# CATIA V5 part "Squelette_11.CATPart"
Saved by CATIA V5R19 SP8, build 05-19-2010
Part number: Squelette_11
Publications: "Diamètre 9-10", "Diamètre 9-11", "Plan dessous", "Plan 9-11", "Plan 9-10 gauche", "Plan 9-10 droite", "Plan profondeur 9-10", "Plan face 11", "ab", "ar"
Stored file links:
  J:\CFAO_IFMA\Squelette_11.CATPart
  J:\CFAO_IFMA\Squelette.CATProduct
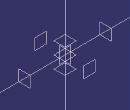
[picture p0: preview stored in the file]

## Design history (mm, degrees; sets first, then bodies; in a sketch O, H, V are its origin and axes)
Parameters
  `Hauteur 11` = 60 mm {= `Diamètre 11-10` +10mm}
  `Longueur 11` = 200 mm
  `Diamètre 11-10` = 50 mm
  `Diamètre 9-11` = 20 mm
  `profondeur 11-10` = 60 mm {= `Diamètre 11-10` +10 mm}
Set1
  Plane1 "Fig.3": linked copy from another document
  Plane2 "Fig.2": linked copy from another document
  Line1 "ar": linked copy from another document
  Line2 "ab": linked copy from another document
Set2
  Plane3 "Plan 9-11": type Offset, RefPlane Plane1, Offset 30 {= `Hauteur 11` /2}
  Plane4 "Plan dessous": type Offset, RefPlane Plane1, Offset 30 {= `Hauteur 11` /2}, reversed
  Plane5 "Plan 11-10 gauche": type Offset, RefPlane Plane2, Offset 100 {= `Longueur 11` /2}
  Plane6 "Plan 11-10 droite": type Offset, RefPlane Plane2, Offset 100 {= `Longueur 11` /2}, reversed
  Plane7: type 2Lines, Element1 Line1, Element2 Line2
  Plane8 "Plan profondeur 11-10": type Offset, RefPlane Plane7, Offset 60 {= `profondeur 11-10`}, reversed
  Plane9 "Plan face 11": type Offset, RefPlane Plane7, Offset 60 {= `profondeur 11-10`}
Body1 (main body)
